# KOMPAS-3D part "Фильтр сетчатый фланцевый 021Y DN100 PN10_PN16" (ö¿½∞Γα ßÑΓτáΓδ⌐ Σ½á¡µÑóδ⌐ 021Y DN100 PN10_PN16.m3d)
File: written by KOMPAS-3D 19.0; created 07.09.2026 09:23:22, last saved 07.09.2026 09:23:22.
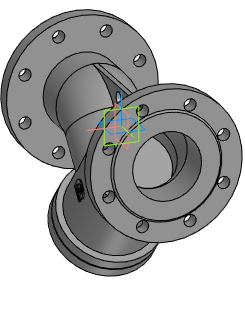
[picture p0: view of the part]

Document properties: Автор: Энергия; Полное имя файла: Z:\3.Личные\sachek\Dendor\_3D для проектировщиков\8.3 Фильтр сетчатый 021Y\021Y_STP\Фильтр сетчатый фланцевый 021Y DN100 PN10_PN16.m3d

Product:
- Part/product: Фильтр сетчатый фланцевый 021Y DN100 PN10_PN16

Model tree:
1. Операция без истории:1  (labels: Фильтр сетчатый фланцевый 021Y DN100 PN10_PN16)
